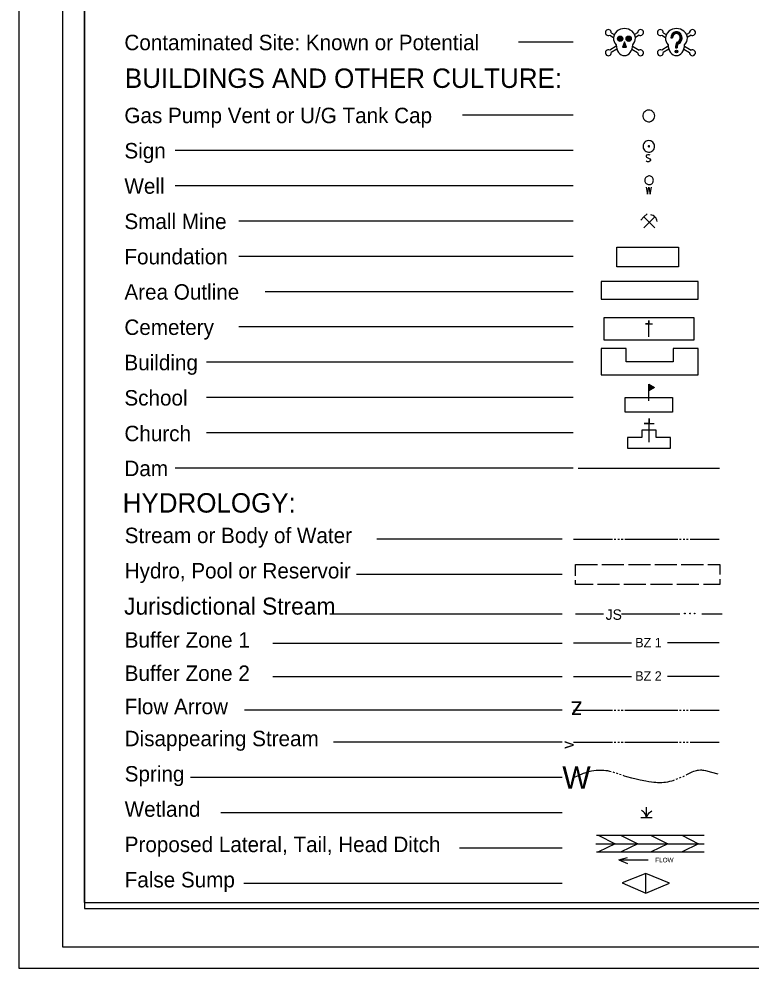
# Model space of a CAD drawing. Extents: x 811508 to 813252, y 647626 to 648754.
# Drawn here: x 811508 to 811937, y 647626 to 648182 of the extents above; entities that cross this region are included whole.
import ezdxf

# ---------------------------------------------------------------- set-up
doc = ezdxf.new("R2010")
doc.units = 0
for name, color, linetype in [('Sheet Cutting Line CELL', 7, 'Continuous'), ('Sheet Plot Border Inside CELL', 7, 'Continuous'), ('Sheet Plot Border Outside CELL', 7, 'Continuous'), ('Sheet_Plan', 7, 'Continuous'), ('Sheet_Symbology', 7, 'Continuous'), ('z - Construction', 7, 'Continuous')]:
    doc.layers.add(name, color=color, linetype=linetype)

msp = doc.modelspace()

# ---------------------------------------------------------------- linework, layer by layer
at = {"layer": 'Sheet Cutting Line CELL'}
for p, q in [((811533.6, 648737.99), (811533.6, 647637.99)), ((811533.6, 647637.99), (813217.6, 647637.99))]:
    msp.add_line(p, q, dxfattribs=at)
at = {"layer": 'Sheet Plot Border Inside CELL'}
msp.add_lwpolyline([(811546.6, 647660.44), (813213.1, 647660.44), (813213.1, 648715.54), (811546.6, 648715.54)], close=True, dxfattribs=at)
at = {"layer": 'Sheet Plot Border Outside CELL'}
msp.add_lwpolyline([(811533.6, 647637.99), (813217.6, 647637.99), (813217.6, 648737.99), (811533.6, 648737.99)], close=True, dxfattribs=at)
at = {"layer": 'Sheet_Plan'}
for q in [(811546.6, 648715.54), (813213.5, 647664.09)]:
    msp.add_line((811546.61, 647664.09), q, dxfattribs=at)
at = {"layer": 'Sheet_Symbology'}
for p, q in [((811854.5, 648172.69), (811856.67, 648171.32)), ((811855.36, 648174.05), (811857.12, 648172.95)), ((811870.81, 648174.05), (811869.05, 648172.95)), ((811871.67, 648172.69), (811869.5, 648171.32)), ((811884.96, 648172.69), (811887.13, 648171.32)), ((811885.82, 648174.05), (811887.58, 648172.95)), ((811901.27, 648174.05), (811899.51, 648172.95)), ((811902.13, 648172.69), (811899.96, 648171.32)), ((811832.99, 648168.51), (811801.07, 648168.51)), ((811863.09, 648168.25), (811863.09, 648168.25)), ((811890.22, 648171.02), (811891.25, 648171.02)), ((811893.55, 648168.77), (811893.55, 648168.77)), ((811858.29, 648166.19), (811854.5, 648163.81)), ((811858.66, 648164.51), (811855.36, 648162.44)), ((811867.52, 648164.51), (811870.81, 648162.44)), ((811867.88, 648166.19), (811871.67, 648163.81)), ((811888.75, 648166.19), (811884.96, 648163.81)), ((811889.12, 648164.51), (811885.82, 648162.44)), ((811893.03, 648166.17), (811893.03, 648165.27)), ((811893.03, 648165.27), (811894.06, 648165.27)), ((811893.18, 648166.17), (811893.18, 648165.27)), ((811893.32, 648166.17), (811893.32, 648165.27)), ((811893.47, 648166.17), (811893.47, 648165.27)), ((811893.62, 648166.17), (811893.62, 648165.27)), ((811893.77, 648166.17), (811893.77, 648165.27)), ((811893.91, 648166.17), (811893.91, 648165.27)), ((811894.06, 648166.17), (811894.06, 648165.27)), ((811897.97, 648164.51), (811901.27, 648162.44)), ((811898.34, 648166.19), (811902.13, 648163.81)), ((811832.99, 648125.72), (811768.21, 648125.72)), ((811832.99, 648105.02), (811599.68, 648105.02)), ((811832.99, 648084.32), (811599.68, 648084.32)), ((811832.99, 648063.62), (811636.94, 648063.62)), ((811874.5, 648066.06), (811872.63, 648064.19)), ((811874.5, 648059.62), (811880.95, 648066.06)), ((811877.73, 648062.84), (811877.36, 648063.21)), ((811877.73, 648062.84), (811880.95, 648059.62)), ((811858.64, 648048.34), (811894.87, 648048.34)), ((811858.64, 648036.77), (811858.64, 648048.34)), ((811894.87, 648048.34), (811894.87, 648036.77)), ((811832.99, 648042.92), (811636.94, 648042.92)), ((811894.87, 648036.77), (811858.64, 648036.77)), ((811906.33, 648028.23), (811849.4, 648028.23)), ((811849.4, 648028.23), (811849.4, 648017.88)), ((811906.33, 648017.88), (811906.33, 648028.23)), ((811832.99, 648022.22), (811652.41, 648022.22)), ((811849.4, 648017.88), (811906.33, 648017.88)), ((811851.11, 648007.14), (811903.75, 648007.14)), ((811851.11, 647993.89), (811851.11, 648007.14)), ((811903.75, 648007.14), (811903.75, 647993.89)), ((811832.99, 648001.52), (811636.94, 648001.52)), ((811864.06, 647988.94), (811849.4, 647988.94)), ((811849.4, 647988.94), (811849.4, 647973.41)), ((811903.75, 647993.89), (811851.11, 647993.89)), ((811864.06, 647981.17), (811864.06, 647988.94)), ((811906.33, 647988.94), (811891.67, 647988.94)), ((811891.67, 647988.94), (811891.67, 647981.17)), ((811906.33, 647973.41), (811906.33, 647988.94)), ((811832.99, 647980.83), (811618.01, 647980.83)), ((811891.67, 647981.17), (811864.06, 647981.17)), ((811849.4, 647973.41), (811906.33, 647973.41)), ((811832.99, 647960.13), (811618.01, 647960.13)), ((811863.56, 647960.13), (811891.22, 647960.13)), ((811863.56, 647951.54), (811863.56, 647960.13)), ((811891.22, 647960.13), (811891.22, 647951.54)), ((811891.22, 647951.54), (811863.56, 647951.54)), ((811832.99, 647939.43), (811618.01, 647939.43)), ((811881.72, 647940.97), (811873.34, 647940.97)), ((811873.34, 647940.97), (811873.34, 647936.79)), ((811881.72, 647936.79), (811881.72, 647940.97)), ((811873.34, 647936.79), (811864.95, 647936.79)), ((811864.95, 647936.79), (811864.95, 647930.49)), ((811890.1, 647936.79), (811881.72, 647936.79)), ((811890.1, 647930.49), (811890.1, 647936.79)), ((811864.95, 647930.49), (811890.1, 647930.49)), ((811832.99, 647918.73), (811599.68, 647918.73)), ((811835.96, 647918.73), (811918.76, 647918.73)), ((811826.51, 647877.13), (811717.84, 647877.13)), ((811833.25, 647877.13), (811856.04, 647877.13)), ((811857.08, 647877.13), (811858.11, 647877.13)), ((811859.15, 647877.13), (811860.18, 647877.13)), ((811861.22, 647877.13), (811862.25, 647877.13)), ((811863.29, 647877.13), (811894.34, 647877.13)), ((811895.37, 647877.13), (811896.41, 647877.13)), ((811897.44, 647877.13), (811898.48, 647877.13)), ((811899.51, 647877.13), (811900.55, 647877.13)), ((811901.58, 647877.13), (811918.63, 647877.13)), ((811834.35, 647862.2), (811847.28, 647862.2)), ((811834.35, 647855.68), (811834.35, 647862.2)), ((811849.87, 647862.2), (811862.81, 647862.2)), ((811865.4, 647862.2), (811878.33, 647862.2)), ((811880.92, 647862.2), (811893.86, 647862.2)), ((811896.44, 647862.2), (811909.38, 647862.2)), ((811826.51, 647856.43), (811706.05, 647856.43)), ((811860.19, 647850.47), (811847.26, 647850.47)), ((811875.72, 647850.47), (811862.78, 647850.47)), ((811891.24, 647850.47), (811878.31, 647850.47)), ((811906.77, 647850.47), (811893.83, 647850.47)), ((811826.51, 647833.04), (811690.3, 647833.04)), ((811833.25, 647816.29), (811867.19, 647816.29)), ((811918.63, 647816.29), (811888.3, 647816.29)), ((811826.51, 647815.84), (811657.03, 647815.84)), ((811826.51, 647796.31), (811657.03, 647796.31)), ((811833.25, 647796.65), (811867.19, 647796.65)), ((811918.63, 647796.65), (811888.3, 647796.65)), ((811826.51, 647776.78), (811640.38, 647776.78)), ((811833.25, 647776.78), (811856.04, 647776.78)), ((811857.08, 647776.78), (811858.11, 647776.78)), ((811859.15, 647776.78), (811860.18, 647776.78)), ((811861.22, 647776.78), (811862.25, 647776.78)), ((811863.29, 647776.78), (811894.34, 647776.78)), ((811895.37, 647776.78), (811896.41, 647776.78)), ((811897.44, 647776.78), (811898.48, 647776.78)), ((811899.51, 647776.78), (811900.55, 647776.78)), ((811901.58, 647776.78), (811918.63, 647776.78)), ((811826.51, 647758.03), (811692.47, 647758.03)), ((811833.25, 647758.03), (811856.04, 647758.03)), ((811857.08, 647758.03), (811858.11, 647758.03)), ((811859.15, 647758.03), (811860.18, 647758.03)), ((811861.22, 647758.03), (811862.25, 647758.03)), ((811863.29, 647758.03), (811894.34, 647758.03)), ((811895.37, 647758.03), (811896.41, 647758.03)), ((811897.44, 647758.03), (811898.48, 647758.03)), ((811899.51, 647758.03), (811900.55, 647758.03)), ((811901.58, 647758.03), (811918.63, 647758.03)), ((811860.17, 647739.35), (811861.15, 647739.01)), ((811826.51, 647737.33), (811608.67, 647737.33)), ((811893.5, 647736.32), (811894.45, 647736.71)), ((811895.42, 647737.09), (811896.37, 647737.49)), ((811826.51, 647716.63), (811626.54, 647716.63)), ((811876.06, 647713.83), (811876.06, 647719.9)), ((811872.78, 647713.83), (811879.38, 647713.83)), ((811846.68, 647703.44), (811909.82, 647703.44)), ((811847.61, 647703.44), (811857.74, 647698.47)), ((811860.76, 647703.44), (811870.89, 647698.47)), ((811878.31, 647703.44), (811888.48, 647698.47)), ((811896.66, 647703.44), (811906.6, 647698.47)), ((811826.51, 647695.93), (811766.3, 647695.93)), ((811846.4, 647698.47), (811909.82, 647698.47)), ((811846.68, 647693.66), (811909.82, 647693.66)), ((811857.74, 647698.47), (811847.89, 647693.66)), ((811870.89, 647698.47), (811861.09, 647693.66)), ((811888.48, 647698.47), (811878.67, 647693.66)), ((811906.6, 647698.47), (811896.94, 647693.66)), ((811859.87, 647689), (811864.84, 647690.4)), ((811859.87, 647689), (811877.1, 647689)), ((811859.87, 647689), (811864.84, 647686.98)), ((811875.72, 647681.04), (811861.67, 647675.58)), ((811875.72, 647669.61), (811875.72, 647681.04)), ((811889.5, 647675.32), (811875.72, 647681.04)), ((811826.51, 647675.23), (811639.93, 647675.23)), ((811861.67, 647675.58), (811875.72, 647669.61)), ((811875.72, 647669.61), (811889.5, 647675.32))]:
    msp.add_line(p, q, dxfattribs=at)
for points in [[(811863.09, 648168.77), (811861.95, 648165.67), (811864.22, 648165.67)], [(811863.09, 648168.25), (811862.21, 648165.85), (811863.96, 648165.85)], [(811863.09, 648167.72), (811862.47, 648166.04), (811863.7, 648166.04)], [(811863.09, 648167.19), (811862.73, 648166.22), (811863.44, 648166.22)], [(811863.09, 648166.67), (811862.99, 648166.4), (811863.19, 648166.4)]]:
    msp.add_lwpolyline(points, close=True, dxfattribs=at)
for points in [[(811880.83, 648125.28), (811880.65, 648126.11), (811880.47, 648126.84), (811880.01, 648127.48), (811879.36, 648128.03), (811878.72, 648128.4), (811877.99, 648128.67), (811877.16, 648128.67), (811876.34, 648128.58), (811875.61, 648128.21), (811874.96, 648127.76), (811874.51, 648127.21), (811874.14, 648126.47), (811873.95, 648125.65), (811873.95, 648124.91), (811874.14, 648124.09), (811874.51, 648123.36), (811874.96, 648122.8), (811875.61, 648122.35), (811876.34, 648121.98), (811877.16, 648121.89), (811877.99, 648121.89), (811878.72, 648122.16), (811879.36, 648122.53), (811880.01, 648123.08), (811880.47, 648123.72), (811880.65, 648124.46), (811880.83, 648125.28)], [(811880.74, 648107.43), (811880.67, 648108.1), (811880.47, 648108.77), (811880.13, 648109.37), (811879.66, 648109.85), (811879.12, 648110.25), (811878.52, 648110.59), (811877.91, 648110.72), (811877.17, 648110.79), (811876.5, 648110.65), (811875.9, 648110.45), (811875.29, 648110.11), (811874.82, 648109.64), (811874.42, 648109.04), (811874.15, 648108.43), (811874.01, 648107.76), (811874.01, 648107.09), (811874.15, 648106.42), (811874.42, 648105.81), (811874.82, 648105.21), (811875.29, 648104.74), (811875.9, 648104.4), (811876.5, 648104.2), (811877.17, 648104.06), (811877.91, 648104.13), (811878.52, 648104.27), (811879.12, 648104.6), (811879.66, 648105), (811880.13, 648105.48), (811880.47, 648106.08), (811880.67, 648106.75), (811880.74, 648107.43)], [(811877.51, 648107.83), (811877.31, 648107.83), (811877.11, 648107.69), (811876.97, 648107.49), (811877.04, 648107.29), (811877.17, 648107.09), (811877.37, 648107.02), (811877.58, 648107.09), (811877.71, 648107.22), (811877.78, 648107.49), (811877.71, 648107.69), (811877.51, 648107.83)], [(811878.16, 648102.24), (811877.51, 648102.54), (811876.76, 648102.54), (811876.08, 648102.24), (811875.78, 648101.72), (811875.78, 648101.53), (811876.11, 648101.04), (811878, 648100.06), (811878.33, 648099.6), (811878.29, 648099.21), (811878, 648098.69), (811877.45, 648098.4), (811876.66, 648098.4), (811876.3, 648098.53), (811875.78, 648098.89)], [(811880.11, 648087.54), (811880.03, 648087.99), (811879.95, 648088.44), (811879.75, 648088.84), (811879.46, 648089.21), (811879.14, 648089.54), (811878.77, 648089.78), (811878.32, 648089.94), (811877.87, 648090.07), (811877.43, 648090.07), (811876.98, 648090.02), (811876.53, 648089.86), (811876.16, 648089.66), (811875.8, 648089.37), (811875.47, 648089.05), (811875.27, 648088.64), (811875.1, 648088.23), (811875.02, 648087.78), (811875.02, 648087.29), (811875.1, 648086.85), (811875.27, 648086.44), (811875.47, 648086.03), (811875.8, 648085.71), (811876.16, 648085.42), (811876.53, 648085.22), (811876.98, 648085.05), (811877.43, 648085.01), (811877.87, 648085.01), (811878.32, 648085.13), (811878.77, 648085.3), (811879.14, 648085.54), (811879.46, 648085.87), (811879.75, 648086.23), (811879.95, 648086.64), (811880.03, 648087.09), (811880.11, 648087.54)], [(811875.89, 648083.55), (811876.54, 648079.41), (811877.39, 648083.55), (811878.23, 648079.41), (811878.95, 648083.55)], [(811877.73, 648062.84), (811874.5, 648066.06), (811876.32, 648067.88)], [(811882.25, 648063.41), (811882.09, 648064.14), (811881.83, 648064.82), (811881.47, 648065.44), (811881, 648065.96), (811880.48, 648066.48), (811879.85, 648066.84), (811879.18, 648067.15), (811878.5, 648067.31)], [(811877.45, 647995.68), (811877.45, 648005.38), (811877.45, 648003.32), (811875.39, 648003.32), (811879.52, 648003.32)], [(811877.43, 647958.2), (811877.43, 647967.9), (811880.67, 647965.99), (811877.43, 647964.08), (811877.62, 647964.39), (811877.62, 647967.63), (811880.29, 647965.95), (811877.81, 647964.5), (811877.85, 647967.33), (811879.99, 647965.95), (811878.04, 647964.85), (811878.04, 647966.98), (811879.64, 647965.95), (811878.27, 647965.19), (811878.27, 647966.64), (811879.3, 647965.99), (811878.46, 647965.49), (811878.46, 647966.3), (811878.99, 647965.99), (811878.65, 647965.8), (811878.61, 647966.03), (811878.73, 647965.99)], [(811877.53, 647933.98), (811877.53, 647947.95), (811877.53, 647944.98), (811874.56, 647944.98), (811880.5, 647944.98)], [(811911.97, 647862.2), (811919.03, 647862.2), (811919.03, 647856.32)], [(811844.67, 647850.47), (811834.35, 647850.47), (811834.35, 647853.09)], [(811919.03, 647853.74), (811919.03, 647850.47), (811909.36, 647850.47)], [(811834.35, 647833.24), (811850.91, 647833.24)], [(811861.3, 647833.24), (811875.82, 647833.24)], [(811875.82, 647833.24), (811895.48, 647833.24)], [(811908.52, 647833.24), (811920.33, 647833.24)], [(811833.26, 647737.33), (811836.2, 647738.56), (811839.15, 647739.8), (811839.88, 647740.09), (811841.19, 647740.54), (811842.2, 647740.81), (811843.71, 647741.16), (811845.24, 647741.43), (811846.52, 647741.59), (811847.66, 647741.68), (811848.66, 647741.7), (811849.53, 647741.7), (811851.07, 647741.61), (811852.23, 647741.5), (811853.08, 647741.37), (811854.36, 647741.12), (811855.24, 647740.91)], [(811856.25, 647740.64), (811856.73, 647740.5), (811857.23, 647740.35)], [(811858.22, 647740.02), (811858.64, 647739.88), (811859.2, 647739.69)], [(811862.14, 647738.68), (811862.92, 647738.4), (811864.37, 647737.98), (811867.16, 647737.24), (811869.25, 647736.71), (811872.39, 647735.99), (811875.56, 647735.33), (811877.32, 647735.02), (811878.88, 647734.78), (811880.25, 647734.63), (811881.45, 647734.52), (811882.5, 647734.47), (811883.43, 647734.45), (811885.03, 647734.47), (811886.24, 647734.55), (811887.14, 647734.65), (811888.48, 647734.85), (811889.8, 647735.13), (811890.79, 647735.4), (811891.66, 647735.66), (811892.52, 647735.97)], [(811897.32, 647737.89), (811897.53, 647737.98), (811898.27, 647738.31)], [(811899.2, 647738.78), (811899.69, 647739.03), (811901.72, 647740.09), (811902.76, 647740.59), (811903.83, 647741.03), (811904.65, 647741.3), (811905.37, 647741.48), (811906.02, 647741.61), (811906.59, 647741.7), (811907.6, 647741.77), (811908.35, 647741.77), (811908.9, 647741.73), (811909.73, 647741.61), (811910.55, 647741.43), (811914.22, 647740.42), (811917.88, 647739.4)], [(811876.06, 647713.83), (811875.9, 647714.55), (811875.69, 647715.28), (811875.33, 647715.96), (811874.86, 647716.58), (811874.34, 647717.15), (811873.72, 647717.57), (811873.04, 647717.93)], [(811876.06, 647713.83), (811876.37, 647714.61), (811876.73, 647715.38), (811877.2, 647716.11), (811877.77, 647716.74), (811878.39, 647717.31), (811879.07, 647717.83)]]:
    msp.add_lwpolyline(points, dxfattribs=at)
for centre, radius in [((811860.59, 648170.54), 1.54), ((811865.58, 648170.54), 1.54), ((811860.59, 648170.54), 1.35), ((811860.59, 648170.54), 1.17), ((811860.59, 648170.54), 0.992), ((811860.59, 648170.54), 0.811), ((811860.59, 648170.54), 0.63), ((811860.59, 648170.54), 0.449), ((811860.59, 648170.54), 0.268), ((811860.59, 648170.54), 0.0869), ((811865.58, 648170.54), 1.35), ((811865.58, 648170.54), 1.17), ((811865.58, 648170.54), 0.992), ((811865.58, 648170.54), 0.811), ((811865.58, 648170.54), 0.63), ((811865.58, 648170.54), 0.449), ((811865.58, 648170.54), 0.268), ((811865.58, 648170.54), 0.0869), ((811893.58, 648163.04), 0.734), ((811893.58, 648163.04), 0.571), ((811893.58, 648163.04), 0.404), ((811893.58, 648163.04), 0.241), ((811893.58, 648163.04), 0.0782)]:
    msp.add_circle(centre, radius, dxfattribs=at)
for centre, start, end in [((811853.65, 648174.18), 355.8976, 299.8062), ((811872.52, 648174.18), 240.1938, 184.1024), ((811884.11, 648174.18), 355.8976, 299.8062), ((811902.98, 648174.18), 240.1938, 184.1024), ((811853.65, 648162.32), 60.1938, 4.1024), ((811872.52, 648162.32), 175.8976, 119.8062), ((811884.11, 648162.32), 60.1938, 4.1024), ((811902.98, 648162.32), 175.8976, 119.8062)]:
    msp.add_arc(centre, 1.72, start, end, dxfattribs=at)
for centre, major_axis, ratio, start_param, end_param in [((811863.09, 648170.81), (6.44, 0), 0.885014, 5.564242, 10.143721), ((811893.55, 648170.81), (6.44, 0), 0.885014, 5.564242, 10.143721), ((811893.55, 648171.02), (0, 3.69), 0.9, 3.567618, 7.853982), ((811893.55, 648171.02), (0, 3.53), 0.9, 3.567618, 7.853982), ((811893.55, 648171.02), (0, 3.37), 0.9, 3.567618, 7.853982), ((811893.55, 648171.02), (0, 3.21), 0.9, 3.567618, 7.853982), ((811893.55, 648171.02), (0, 3.04), 0.9, 3.567618, 7.853982), ((811893.55, 648171.02), (0, 2.88), 0.9, 3.567618, 7.853982), ((811893.55, 648171.02), (0, 2.72), 0.9, 3.567618, 7.853982), ((811893.55, 648171.02), (0, 2.55), 0.9, 3.567618, 7.853982), ((811863.09, 648167.12), (0, -6.44), 0.752542, 4.722735, 7.843636), ((811893.55, 648167.12), (0, -6.44), 0.752542, 4.722735, 7.843636), ((811895.53, 648166.17), (0, 2.77), 0.9, 0.426026, 1.570796), ((811895.53, 648166.17), (0, 2.61), 0.9, 0.426026, 1.570796), ((811895.53, 648166.17), (0, 2.45), 0.9, 0.426026, 1.570796), ((811895.53, 648166.17), (0, 2.28), 0.9, 0.426026, 1.570796), ((811895.53, 648166.17), (0, 2.12), 0.9, 0.426026, 1.570796), ((811895.53, 648166.17), (0, 1.96), 0.9, 0.426026, 1.570796), ((811895.53, 648166.17), (0, 1.79), 0.9, 0.426026, 1.570796), ((811895.53, 648166.17), (0, 1.63), 0.9, 0.426026, 1.570796)]:
    msp.add_ellipse(centre, major_axis=major_axis, ratio=ratio, start_param=start_param, end_param=end_param, dxfattribs=at)
for centre in [(811898.52, 647833.53), (811901.58, 647833.53), (811904.26, 647833.53)]:
    msp.add_ellipse(centre, major_axis=(0, 0.204), ratio=0.938496, dxfattribs=at)
at = {"layer": 'z - Construction'}
for p, q in [((811508.14, 648754), (811508.14, 647625.63)), ((811508.14, 647625.63), (813251.99, 647625.63))]:
    msp.add_line(p, q, dxfattribs=at)

# ---------------------------------------------------------------- texts
at = {"layer": 'Sheet_Symbology'}
for s, height, p in [('Contaminated Site: Known or Potential', 9.056, (811569.94, 648163.83)), ('BUILDINGS AND OTHER CULTURE:', 11.3847, (811570.22, 648141.71)), ('Gas Pump Vent or U/G Tank Cap', 9.056, (811569.94, 648121.04)), ('Sign', 9.056, (811569.95, 648100.35)), ('Well', 9.056, (811569.95, 648079.65)), ('Small Mine', 9.056, (811569.95, 648058.94)), ('Foundation', 9.056, (811569.95, 648038.24)), ('Area Outline', 9.056, (811569.95, 648017.54)), ('Cemetery', 9.056, (811569.94, 647996.85)), ('Building', 9.056, (811569.95, 647976.15)), ('School', 9.056, (811569.94, 647955.46)), ('Church', 9.056, (811569.96, 647934.56)), ('Dam', 9.056, (811569.95, 647914.06)), ('HYDROLOGY:', 11.385, (811568.93, 647892.68)), ('Stream or Body of Water', 9.056, (811570.11, 647874.78)), ('Hydro, Pool or Reservoir', 9.056, (811570.11, 647854.08)), ('Jurisdictional Stream', 9.9833, (811569.76, 647832.84)), ('JS', 6.112, (811852.06, 647829.8)), ('Buffer Zone 1', 9.056, (811570.11, 647813.5)), ('BZ 1', 5.501, (811869.41, 647813.69)), ('Buffer Zone 2', 9.056, (811570.11, 647793.97)), ('BZ 2', 5.501, (811869.41, 647794.13)), ('Flow Arrow', 9.056, (811570.11, 647774.44)), ('Disappearing Stream', 9.056, (811570.11, 647755.69)), ('Spring', 9.056, (811570.11, 647734.99)), ('W', 13.2, (811826.66, 647730.73)), ('Wetland', 9.056, (811570.11, 647714.29)), ('Proposed Lateral, Tail, Head Ditch', 9.056, (811570.11, 647693.59)), ('FLOW', 2.684, (811881.18, 647687.6)), ('False Sump', 9.056, (811570.11, 647672.89))]:
    msp.add_text(s, height=height, dxfattribs=at).set_placement(p)
for s, height, rotation, p in [('z', 10.35, 180, (811838.43, 647781.96)), ('v', 6.83, 89.7591, (811833.25, 647754.16))]:
    msp.add_text(s, height=height, rotation=rotation, dxfattribs=at).set_placement(p)

doc.saveas('drawing.dxf')
